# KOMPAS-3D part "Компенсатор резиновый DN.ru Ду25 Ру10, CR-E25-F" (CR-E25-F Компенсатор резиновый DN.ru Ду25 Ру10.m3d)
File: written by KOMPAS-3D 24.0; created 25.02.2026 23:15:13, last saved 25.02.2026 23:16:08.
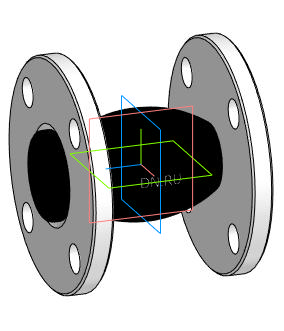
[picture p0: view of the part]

Document properties: Автор: DN.RU; Полное имя файла: D:\PROJECT CAD\DN.RU\...178(4)(ACTUALE). CR-E25-F Компенсатор резиновый DN.ru Ру10-16\DN25_PN10\CR-E25-F Компенсатор резиновый DN.ru Ду25 Ру10.m3d

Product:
- Body: Твердое тело2  | qty 1
    Масса: 1.965785
- Part/product: Компенсатор резиновый DN.ru Ду25 Ру10  | designation CR-E25-F
    Масса: 2.5
    Раздел спецификации: Прочие изделия
    Комментарий: D140-02159
    Примечание: D140-02159
    additional columns: Типовые

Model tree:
1. Твердое тело2  (labels: Твердое тело2)

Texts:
  CR-E25-F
